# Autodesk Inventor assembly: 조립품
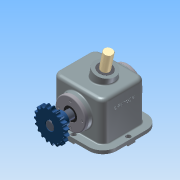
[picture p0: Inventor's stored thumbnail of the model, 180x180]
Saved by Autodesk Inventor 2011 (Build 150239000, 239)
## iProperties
Company: 한국ATC센터
Created: 2014-07
Part Number: 조립품
Document SubType Name: Assembly
Designer: KYOUNG IL JANG
Mass: 6548.08 g
Surface Area: 3444.33 cm^2
Volume: 1649.71 cm^3
Density: 3.96923 g/cm^3
Author: KYOUNG IL JANG
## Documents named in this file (13)
- C:\Users\SDA16\Desktop\441122V1010\조립품.iam
- C:\Users\SDA16\Desktop\441122V1010\뒤커버.ipt
- C:\Users\SDA16\Desktop\441122V1010\앞커버.ipt
- C:\Users\SDA16\Desktop\441122V1010\베어링 6205.ipt
- C:\Users\SDA16\Desktop\441122V1010\편심축.ipt
- C:\Users\SDA16\Desktop\441122V1010\슬라이드.ipt
- C:\Users\SDA16\Desktop\441122V1010\부시.ipt
- C:\Users\SDA16\Desktop\441122V1010\오일실.ipt
- C:\Users\SDA16\Desktop\441122V1010\키 8x8.ipt
- C:\Users\SDA16\Desktop\441122V1010\M4x0.5.ipt
- C:\Users\SDA16\Desktop\441122V1010\5-체인 스프로킷.ipt
- C:\Users\SDA16\Desktop\441122V1010\멈춤나사 M5x0.5.ipt
- C:\Users\SDA16\Desktop\441122V1010\본체.ipt
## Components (9 placed, 2 different names)
1. 5-체인 스프로킷:1 — 각도:2
2. M4x0.5:1
3. M4x0.5:2
4. M4x0.5:3
5. M4x0.5:7
6. M4x0.5:4
7. M4x0.5:5
8. M4x0.5:6
9. M4x0.5:8
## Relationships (1: Angle 1)
- 각도:2 [Angle]: 5-체인 스프로킷:1
